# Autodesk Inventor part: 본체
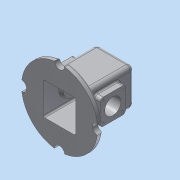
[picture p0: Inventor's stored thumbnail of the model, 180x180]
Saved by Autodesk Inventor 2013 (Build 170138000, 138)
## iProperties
Created: 2018-07
Part Number: 본체
Material: 알루미늄 6061
Document SubType Name: Modeling
Designer: Administrator
Density: 2.71 g/cm^3
Mass: 912.845 g
Surface Area: 1019.25 cm^2
Volume: 336.843 cm^3
Author: Administrator
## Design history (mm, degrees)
sketch "스케치1"
  geometry: L1 (0, 0)-(-99.447, 0); L2 (0, 0)-(0, -89.26); C1 r 75 at (0, 0); 1 further point
  constraints: 4 end point, 1 centre point, 1 coincident, 1 horizontal, 1 perpendicular
  dimensions: "d0" = 150 diameter of C1
extrude "돌출1" new body sketch "스케치1" distance "d2" = 10; taper "d3" = 0 deg
sketch "스케치2"
  geometry: L1 (0, 0)-(98.616, 0); L2 (0, 0)-(0, 93.63); C1 r 10 at (0, 75); C2 r 10 at (-75, 0); C3 r 10 at (0, -75); C4 r 10 at (75, 0)
  constraints: 4 centre point, 4 end point, 1 horizontal, 1 perpendicular, 1 point on line, 1 vertical alignment, 10 other
  dimensions: "d4" = 20 diameter of C1; "d8" = 360 deg dimension on L1.start C1.centre (derived)
extrude "돌출2" cut sketch "스케치2" distance "d10" = 10; taper "d11" = 0 deg
sketch "스케치3"
  geometry: L1 (-37, -37)-(37, -37); L2 (37, -37)-(37, 37); L3 (37, 37)-(-37, 37); L4 (-37, 37)-(-37, -37); L5 (-37, -37)-(37, 37); L6 (37, -37)-(-37, 37); A1 r 75 centre (0, 0) between (9.978, -74.333) and (74.333, -9.978) reference
  constraints: 12 end point, 2 midpoint, 2 parallel, 1 horizontal, 1 perpendicular
  dimensions: "d12" = 74 distance between parallel lines of L2 L4; "d14" = 74 distance between parallel lines of L3 L1
extrude "돌출3" join sketch "스케치3" distance "d15" = 100; taper "d16" = 0 deg
sketch "스케치4"
  geometry: L1 (-20, -20)-(20, -20); L2 (20, -20)-(20, 20); L3 (20, 20)-(-20, 20); L4 (-20, 20)-(-20, -20); L5 (-20, -20)-(20, 20); L6 (20, -20)-(-20, 20); 1 further point
  constraints: 12 end point, 2 midpoint, 2 parallel, 1 horizontal, 1 perpendicular
  dimensions: "d17" = 40 distance between parallel lines of L3 L1; "d19" = 40 distance between parallel lines of L4 L2
extrude "돌출4" join sketch "스케치4" distance "d20" = 7; taper "d21" = 0 deg
sketch "스케치5"
  geometry: C1 r 17.5 at (0, 0); 1 further point
  constraints: 1 centre point, 1 coincident
  dimensions: "d24" = 35 diameter of C1
extrude "돌출5" join sketch "스케치5" distance "d22" = 3; taper "d23" = 0 deg
sketch "스케치6"
  geometry: L1 (-32, 0)-(-32, 105); L2 (-32, 105)-(32, 105); L3 (32, 105)-(32, 0); L4 (32, 0)-(-32, 0); L5 (37, 110)-(-37, 110) reference; L6 (-37, 10)-(-37, 110) reference; L7 (37, 10)-(37, 110) reference; 1 further point
  constraints: 8 end point, 2 parallel, 1 midpoint, 1 perpendicular, 1 vertical
  dimensions: "d26" = 5 distance between parallel lines of L5 L2; "d27" = 5 distance between parallel lines of L7 L3; "d28" = 5 distance between parallel lines of L6 L1
extrude "돌출6" cut sketch "스케치6" stored distance "d29" = 64; taper "d30" = 0 deg
sketch "스케치8"
  geometry: L1 (12, 20)-(62, 20); L2 (62, 20)-(62, 70); L3 (62, 70)-(12, 70); L4 (12, 70)-(12, 20); L5 (12, 20)-(62, 70); L6 (62, 20)-(12, 70); L7 (37, -10)-(37, 143.948); L8 (46.978, -10)-(111.333, -10) reference; 2 further points
  constraints: 14 end point, 3 midpoint, 3 parallel, 1 horizontal, 1 perpendicular, 1 point on line
  dimensions: "d31" = 50 distance between parallel lines of L3 L1; "d33" = 50 distance between parallel lines of L4 L2; "d34" = 55 distance from line of point (37, 45) L8
extrude "돌출7" join sketch "스케치8" distance "d35" = 13; taper "d36" = 0 deg
sketch "스케치9"
  geometry: L1 (12, 20)-(62, 20); L2 (62, 20)-(62, 70); L3 (62, 70)-(12, 70); L4 (12, 70)-(12, 20); L5 (12, 20)-(62, 70); L6 (62, 20)-(12, 70); L7 (37, -10)-(37, 135.197); L8 (46.978, -10)-(111.333, -10) reference; 2 further points
  constraints: 14 end point, 3 midpoint, 3 parallel, 1 horizontal, 1 perpendicular, 1 point on line
  dimensions: "d37" = 50 distance between parallel lines of L3 L1; "d39" = 50 distance between parallel lines of L4 L2; "d40" = 55 distance from line of point (37, 45) L8
extrude "돌출8" join sketch "스케치9" distance "d41" = 13; taper "d42" = 0 deg
sketch "스케치10"
  geometry: L1 (-89.326, 55)-(79.755, 55); L2 (32, 0)-(-32, 0) reference; L3 (-32, 80)-(-25, 77.452); L4 (-25, 77.452)-(-25, 32.548); L5 (-25, 32.548)-(-32, 30); L6 (-32, 30)-(-32, 80); L7 (-32, 0)-(-32, 105) reference; L8 (32, 105)-(32, 0) reference; L9 (-32, 55)-(-32, 80); L10 (-25, 55)-(-25, 77.452); L11 (-25, 55)-(-32, 55); L12 (0, 0)-(0, 157.178); L13 (25, 55)-(25, 77.452); L14 (32, 55)-(32, 80); L15 (32, 80)-(25, 77.452); L16 (25, 55)-(32, 55)
  constraints: 26 end point, 4 symmetric about line, 2 collinear, 2 midpoint, 2 perpendicular, 1 horizontal, 1 point on line, 1 vertical
  dimensions: "d43" = 55 distance between parallel lines of L1 L2; "d45" = 7 distance between parallel lines of L7 L4; "d46" = 110 deg angle of L5 L7; "d47" = 110 deg angle of L7 L3; "d48" = 7 distance between parallel lines of L4 L6; "d49" = 25 distance from line of L3.start L1
revolve "회전1" sketch "스케치10" stored, may be unused: angle "d50" = 90 deg
sketch "스케치11"
  geometry: L1 (12, 70)-(12, 20) reference; L2 (12, 20)-(62, 70); L3 (62, 20)-(12, 70); C1 r 16 at (37, 45); 1 further point
  constraints: 4 end point, 1 centre point, 1 perpendicular, 1 point on line
  dimensions: "d51" = 32 diameter of C1
extrude "돌출9" cut sketch "스케치11" distance "d53" = 110; taper "d54" = 0 deg
sketch "스케치12"
  geometry: C1 r 17.5 at (0, 0) reference; C2 r 14 at (0, 0)
  constraints: 1 centre point, 1 coincident
  dimensions: "d55" = 28 diameter of C2
extrude "돌출10" cut sketch "스케치12" distance "d57" = 4; taper "d58" = 0 deg
sketch "스케치13"
  geometry: C1 r 14 at (0, 0) reference; C2 r 10.5 at (0, 0)
  constraints: 1 centre point, 1 coincident
  dimensions: "d59" = 21 diameter of C2
extrude "돌출11" cut sketch "스케치13" distance "d61" = 110; taper "d62" = 0 deg
fillet "모깎기1" dims "d63" = 6
fillet "모깎기2" dims "d64" = 6
sketch "스케치15"
  geometry: A1 r 6 centre (56, 26) between (56, 20) and (62, 26) reference; A2 r 6 centre (56, 64) between (62, 64) and (56, 70) reference; A3 r 6 centre (18, 64) between (18, 70) and (12, 64) reference; A4 r 6 centre (18, 26) between (12, 26) and (18, 20) reference; 5 further points
  constraints: 4 coincident
hole "구멍1" sketch "스케치15" at (18, 64), (18, 26), (56, 26), (56, 64) diameter "d65" = 3.459; stored, may be unused: countersink angle "d69" = 90 deg, drill point angle "d71" = 118 deg; dims "d66" = 8, "d67" = 4, "d68" = 2, "d70" = 10
fillet "모깎기3" dims "d72" = 8
fillet "모깎기4" dims "d73" = 3
fillet "모깎기5" dims "d74" = 3
fillet "모깎기6" dims "d75" = 3
fillet "모깎기7" dims "d76" = 3
fillet "모깎기8" dims "d77" = 3
fillet "모깎기9" dims "d78" = 3
sketch "스케치17"
  geometry: L1 (46.5, 18)-(11.5, 18) reference; L2 (66, -89)-(66, 0) reference; 2 further points
  constraints: 1 other
  dimensions: "d79" = 30 distance from line of L1 point (29, -12); "d80" = 37 distance from line of point (29, -12) L2
feature "엠보싱1" sketch "스케치17" dims "d81" = 0.5, "d82" = 0
node "솔리드1"
mirror "대칭1"
